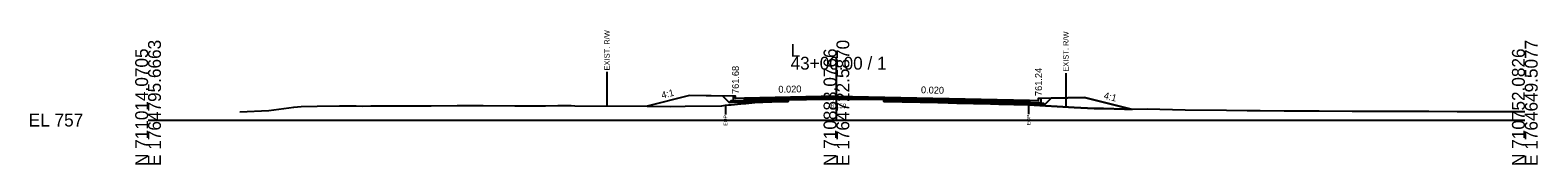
# Model space of a CAD drawing. Extents: x -26 to 5303, y -10 to 9578.
# Drawn here: x 2974.3 to 3302.8, y 2990.3 to 3019.3 of the extents above; entities that cross this region are included whole.
import ezdxf

# ---------------------------------------------------------------- set-up
doc = ezdxf.new("R2010")
doc.units = 0
for name, color, linetype in [('Default', 7, 'Continuous'), ('Exist CMT Pavement', 7, 'Continuous'), ('Exist Cross Section Cell', 7, 'Continuous'), ('Exist XS Ground Line', 7, 'Continuous'), ('Old_Level_10', 7, 'Continuous'), ('Old_Level_3', 7, 'Continuous'), ('Prop CMT Conc Surface', 7, 'Continuous'), ('Prop CMT Concrete Structures', 7, 'Continuous'), ('Prop CMT Pvmt Course 1', 7, 'Continuous'), ('Prop CMT Pvmt Course 1 CG', 7, 'Continuous'), ('Prop CMT Pvmt Course 2', 7, 'Continuous'), ('Prop CMT Pvmt Course 3', 7, 'Continuous'), ('Prop CMT Pvmt Surface', 7, 'Continuous'), ('Prop CMT Slope Grass', 7, 'Continuous'), ('Prop CMT Subgrade Earthwork', 7, 'Continuous'), ('Prop XS Earthwork Shape', 7, 'Continuous'), ('Prop XS Hydro Elevations', 7, 'Continuous'), ('Prop XS SE Text', 7, 'Continuous'), ('Prop XS Side Slope Text', 7, 'Continuous'), ('Prop XS Wedging', 7, 'Continuous')]:
    doc.layers.add(name, color=color, linetype=linetype)

msp = doc.modelspace()

# ---------------------------------------------------------------- linework, layer by layer
at = {"layer": 'Exist CMT Pavement'}
msp.add_lwpolyline([(3139.45, 3004.41), (3140.58, 3004.46), (3141.3, 3004.48), (3142.48, 3004.5), (3143.14, 3004.51), (3143.5, 3004.52), (3144.97, 3004.53), (3146.37, 3004.56), (3146.81, 3004.57), (3147.61, 3004.58), (3148.65, 3004.59), (3149.23, 3004.6), (3150, 3004.59), (3151.27, 3004.57), (3152.33, 3004.56), (3152.74, 3004.56), (3154.16, 3004.58), (3154.95, 3004.57), (3156, 3004.56), (3157.88, 3004.57), (3160.36, 3004.5)], dxfattribs=at)
at = {"layer": 'Exist Cross Section Cell'}
for p, q in [((3150, 3000), (3150, 3013.79)), ((3000, 3000), (3150, 3000)), ((3150, 3000), (3300, 3000))]:
    msp.add_line(p, q, dxfattribs=at)
at = {"layer": 'Exist XS Ground Line'}
msp.add_lwpolyline([(3020, 3001.81), (3026.32, 3002.06), (3031.79, 3002.85), (3033.36, 3002.98), (3036.83, 3003), (3041.72, 3003.07), (3045.38, 3003.07), (3046.62, 3003.04), (3048.56, 3003.08), (3061.71, 3003.14), (3067.38, 3003.15), (3071.61, 3003.15), (3073.02, 3003.15), (3079.91, 3003.12), (3086.59, 3003.12), (3089.29, 3003.15), (3092.22, 3003.15), (3093.03, 3003.14), (3109.61, 3003.06), (3113.8, 3002.98), (3117.01, 3003), (3125.02, 3003.14), (3125.83, 3003.23), (3126.49, 3003.29), (3127.09, 3003.32), (3129.19, 3003.52), (3130.27, 3003.6), (3132.22, 3003.81), (3134.92, 3003.95), (3135.79, 3003.99), (3137.78, 3004.24), (3139.45, 3004.41), (3140.58, 3004.46), (3141.3, 3004.48), (3142.48, 3004.5), (3143.14, 3004.51), (3143.5, 3004.52), (3144.79, 3004.54), (3146.37, 3004.56), (3146.81, 3004.57), (3147.61, 3004.58), (3148.65, 3004.59), (3149.23, 3004.6), (3150, 3004.59), (3151.27, 3004.57), (3152.09, 3004.56), (3152.74, 3004.56), (3154.16, 3004.58), (3154.95, 3004.57), (3156, 3004.56), (3157.88, 3004.57), (3159.68, 3004.57), (3160.68, 3004.5), (3163.01, 3004.31), (3163.54, 3004.28), (3165.19, 3004.18), (3166.41, 3004.12), (3168.14, 3004.05), (3168.86, 3004.01), (3169.27, 3003.98), (3170.7, 3003.92), (3172.13, 3003.86), (3172.54, 3003.84), (3173.27, 3003.81), (3174.38, 3003.78), (3174.99, 3003.76), (3176.21, 3003.72), (3178.05, 3003.68), (3178.4, 3003.67), (3180.72, 3003.6), (3181.73, 3003.58), (3183.64, 3003.54), (3186.44, 3003.48), (3187.24, 3003.46), (3188.66, 3003.43), (3189.02, 3003.42), (3189.97, 3003.38), (3190.45, 3003.37), (3191.88, 3003.32), (3201.79, 3002.72), (3206.14, 3002.55), (3208.18, 3002.54), (3212.8, 3002.38), (3213.27, 3002.4), (3214.51, 3002.39), (3217.82, 3002.46), (3220.46, 3002.39), (3225.98, 3002.24), (3235.01, 3002.15), (3239.48, 3002.1), (3242.36, 3002.1), (3247.53, 3002), (3249.71, 3002.01), (3250.93, 3001.99), (3255.22, 3001.98), (3262.38, 3001.97), (3268.06, 3001.94), (3271.77, 3001.93), (3273.84, 3001.92), (3279.12, 3001.92), (3285.29, 3001.87), (3288.59, 3001.87), (3296.74, 3001.89), (3300, 3001.86)], dxfattribs=at)
at = {"layer": 'Old_Level_10'}
for p, q in [((3100, 3010.51), (3100, 3003.11)), ((3200, 3010.23), (3200, 3002.83)), ((3125.81, 3003.23), (3125.81, 3001.18)), ((3191.88, 3003.32), (3191.88, 3001.27))]:
    msp.add_line(p, q, dxfattribs=at)
at = {"layer": 'Prop CMT Conc Surface'}
for points in [[(3128, 3004.68), (3128, 3005.18), (3127.5, 3005.18)], [(3130, 3004.8), (3128, 3004.68)], [(3192.04, 3004.36), (3194.04, 3004.24)], [(3194.04, 3004.24), (3194.04, 3004.74), (3194.54, 3004.74)]]:
    msp.add_lwpolyline(points, dxfattribs=at)
at = {"layer": 'Prop CMT Concrete Structures'}
for points in [[(3130, 3004.8), (3128, 3004.68), (3128, 3005.18), (3127.5, 3005.18)], [(3127.5, 3005.18), (3127.5, 3004.17), (3130, 3004.22)], [(3130, 3004.22), (3130, 3004.8)], [(3192.04, 3004.36), (3194.04, 3004.24), (3194.04, 3004.74), (3194.54, 3004.74)], [(3194.54, 3004.74), (3194.54, 3003.73), (3192.04, 3003.78)], [(3192.04, 3003.78), (3192.04, 3004.36)]]:
    msp.add_lwpolyline(points, dxfattribs=at)
at = {"layer": 'Prop CMT Pvmt Course 1'}
for points in [[(3150, 3005.2), (3130, 3004.8)], [(3130, 3004.8), (3130, 3004.55)], [(3130, 3004.55), (3139.45, 3004.74)], [(3139.45, 3004.74), (3150, 3004.95)], [(3139.45, 3004.74), (3139.45, 3004.74)], [(3150, 3004.95), (3150, 3005.2)], [(3150, 3005.2), (3192.04, 3004.36)], [(3150, 3004.95), (3150, 3004.95), (3150, 3004.95)], [(3160.36, 3004.75), (3150, 3004.95)], [(3192.04, 3004.11), (3160.36, 3004.75)], [(3160.36, 3004.75), (3160.36, 3004.75)], [(3192.04, 3004.36), (3192.04, 3004.11)]]:
    msp.add_lwpolyline(points, dxfattribs=at)
at = {"layer": 'Prop CMT Pvmt Course 1 CG'}
for points in [[(3130, 3004.22), (3127, 3004.16), (3126.66, 3003.82)], [(3126.66, 3003.82), (3130, 3003.89)], [(3130, 3003.89), (3130, 3004.22)], [(3192.04, 3003.78), (3195.04, 3003.72), (3195.38, 3003.38)], [(3192.04, 3003.45), (3192.04, 3003.78)], [(3195.38, 3003.38), (3192.04, 3003.45)]]:
    msp.add_lwpolyline(points, dxfattribs=at)
at = {"layer": 'Prop CMT Pvmt Course 2'}
for points in [[(3139.45, 3004.74), (3130, 3004.55)], [(3130, 3004.55), (3130, 3004.22)], [(3130, 3004.22), (3139.45, 3004.41)], [(3139.45, 3004.41), (3139.45, 3004.74)], [(3160.36, 3004.41), (3160.36, 3004.75)], [(3160.36, 3004.75), (3192.04, 3004.11)], [(3192.04, 3003.78), (3160.36, 3004.41)], [(3192.04, 3004.11), (3192.04, 3003.78)]]:
    msp.add_lwpolyline(points, dxfattribs=at)
at = {"layer": 'Prop CMT Pvmt Course 3'}
for points in [[(3139.45, 3004.41), (3130, 3004.22)], [(3130, 3004.22), (3130, 3003.89)], [(3130, 3003.89), (3139.45, 3004.08)], [(3139.45, 3004.08), (3139.45, 3004.41)], [(3160.36, 3004.41), (3192.04, 3003.78)], [(3160.36, 3004.08), (3160.36, 3004.41)], [(3192.04, 3003.45), (3160.36, 3004.08)], [(3192.04, 3003.78), (3192.04, 3003.45)]]:
    msp.add_lwpolyline(points, dxfattribs=at)
at = {"layer": 'Prop CMT Pvmt Surface'}
for points in [[(3150, 3005.2), (3130, 3004.8)], [(3150, 3005.2), (3192.04, 3004.36)]]:
    msp.add_lwpolyline(points, dxfattribs=at)
at = {"layer": 'Prop CMT Slope Grass'}
for points in [[(3127.5, 3005.18), (3118, 3005.37), (3108.76, 3003.06)], [(3194.54, 3004.74), (3204.04, 3004.93), (3214.2, 3002.39)]]:
    msp.add_lwpolyline(points, dxfattribs=at)
at = {"layer": 'Prop CMT Subgrade Earthwork'}
for p, q in [((3139.45, 3004.08), (3139.45, 3004.41)), ((3160.36, 3004.08), (3160.36, 3004.5))]:
    msp.add_line(p, q, dxfattribs=at)
for points in [[(3130, 3003.89), (3126.66, 3003.82), (3125.25, 3005.23)], [(3139.45, 3004.08), (3130, 3003.89)], [(3160.36, 3004.08), (3192.04, 3003.45)], [(3192.04, 3003.45), (3195.38, 3003.38), (3196.79, 3004.79)]]:
    msp.add_lwpolyline(points, dxfattribs=at)
at = {"layer": 'Prop XS Earthwork Shape'}
for points in [[(3108.76, 3003.06), (3109.61, 3003.06), (3113.8, 3002.98), (3117.01, 3003), (3125.02, 3003.14), (3125.83, 3003.23), (3126.49, 3003.29), (3127.09, 3003.32), (3129.19, 3003.52), (3130.27, 3003.6), (3132.22, 3003.81), (3133.95, 3003.91), (3134.92, 3003.95), (3135.79, 3003.99), (3135.92, 3004.01), (3130, 3003.89), (3126.66, 3003.82), (3125.25, 3005.23), (3118, 3005.37)], [(3125.25, 3005.23), (3118, 3005.37), (3108.76, 3003.06), (3109.61, 3003.06), (3113.8, 3002.98), (3117.01, 3003), (3125.02, 3003.14), (3125.83, 3003.23), (3126.49, 3003.29), (3127.09, 3003.32), (3129.19, 3003.52), (3130.27, 3003.6), (3132.22, 3003.81), (3133.95, 3003.91), (3134.92, 3003.95), (3135.79, 3003.99), (3135.92, 3004.01), (3130, 3003.89), (3126.66, 3003.82)], [(3137.78, 3004.24), (3139.45, 3004.41), (3139.45, 3004.08), (3135.92, 3004.01), (3137.35, 3004.19)], [(3139.45, 3004.08), (3139.45, 3004.41), (3137.78, 3004.24), (3137.35, 3004.19), (3135.92, 3004.01)], [(3160.36, 3004.08), (3160.36, 3004.5), (3160.68, 3004.5), (3161.51, 3004.42), (3163.01, 3004.31), (3163.54, 3004.28), (3165.19, 3004.18), (3166.41, 3004.12), (3167.03, 3004.1), (3168.14, 3004.05), (3168.86, 3004.01), (3169.27, 3003.98), (3170.7, 3003.92), (3172.13, 3003.86), (3172.54, 3003.84)], [(3166.41, 3004.12), (3167.03, 3004.1), (3168.14, 3004.05), (3168.86, 3004.01), (3169.27, 3003.98), (3170.7, 3003.92), (3172.13, 3003.86), (3172.54, 3003.84), (3160.36, 3004.08), (3160.36, 3004.5), (3160.68, 3004.5), (3161.51, 3004.42), (3163.01, 3004.31), (3163.54, 3004.28), (3165.19, 3004.18)], [(3204.04, 3004.93), (3214.2, 3002.39), (3213.27, 3002.4), (3212.8, 3002.38), (3208.18, 3002.54), (3206.14, 3002.55), (3201.79, 3002.72), (3191.88, 3003.32), (3190.45, 3003.37), (3189.97, 3003.38), (3189.02, 3003.42), (3188.66, 3003.43), (3187.24, 3003.46), (3186.44, 3003.48), (3185.4, 3003.5), (3183.58, 3003.54), (3181.73, 3003.58), (3180.72, 3003.6), (3179.89, 3003.63), (3178.4, 3003.67), (3178.05, 3003.68), (3176.21, 3003.72), (3174.99, 3003.76), (3174.38, 3003.78), (3173.27, 3003.81), (3172.54, 3003.84), (3192.04, 3003.45), (3195.38, 3003.38), (3196.79, 3004.79)], [(3189.02, 3003.42), (3189.97, 3003.38), (3190.45, 3003.37), (3191.88, 3003.32), (3201.79, 3002.72), (3206.14, 3002.55), (3208.18, 3002.54), (3212.8, 3002.38), (3213.27, 3002.4), (3214.2, 3002.39), (3204.04, 3004.93), (3196.79, 3004.79), (3195.38, 3003.38), (3192.04, 3003.45), (3172.54, 3003.84), (3173.27, 3003.81), (3174.38, 3003.78), (3174.99, 3003.76), (3176.21, 3003.72), (3178.05, 3003.68), (3178.4, 3003.67), (3179.89, 3003.63), (3180.72, 3003.6), (3181.73, 3003.58), (3183.58, 3003.54), (3185.4, 3003.5), (3186.44, 3003.48), (3187.24, 3003.46), (3188.66, 3003.43)]]:
    msp.add_lwpolyline(points, close=True, dxfattribs=at)
at = {"layer": 'Prop XS Wedging'}
msp.add_lwpolyline([(3139.45, 3004.41), (3139.45, 3004.74), (3140.58, 3004.76), (3141.3, 3004.78), (3142.48, 3004.8), (3143.14, 3004.82), (3143.5, 3004.82), (3144.97, 3004.85), (3146.37, 3004.88), (3146.81, 3004.89), (3147.61, 3004.91), (3148.65, 3004.93), (3149.23, 3004.94), (3150, 3004.95), (3151.27, 3004.93), (3152.33, 3004.91), (3152.74, 3004.9), (3154.16, 3004.87), (3154.95, 3004.85), (3156, 3004.83), (3157.88, 3004.8), (3160.68, 3004.74), (3160.68, 3004.49), (3157.88, 3004.57), (3156, 3004.56), (3154.95, 3004.57), (3154.16, 3004.58), (3152.74, 3004.56), (3152.33, 3004.56), (3151.27, 3004.57), (3150, 3004.59), (3149.23, 3004.6), (3148.65, 3004.59), (3147.61, 3004.58), (3146.81, 3004.57), (3146.37, 3004.56), (3144.97, 3004.53), (3143.5, 3004.52), (3143.14, 3004.51), (3142.48, 3004.5), (3141.3, 3004.48), (3140.58, 3004.46)], close=True, dxfattribs=at)

# ---------------------------------------------------------------- texts
at = {"layer": 'Default'}
msp.add_text('-', height=0.0001, dxfattribs=at).set_placement((3000, 3000))
at = {"layer": 'Exist Cross Section Cell'}
for s, p in [('E 1764795.6663', (3002.8, 2990)), ('E 1764722.5870', (3152.8, 2990)), ('E 1764649.5077', (3302.8, 2990)), ('N 711014.0705', (3000, 2990)), ('N 710883.0766', (3150, 2990)), ('N 710752.0826', (3300, 2990))]:
    msp.add_text(s, height=2.8, rotation=90, dxfattribs=at).set_placement(p)
for s, p in [('L', (3140, 3013.79)), ('43+00.00 / 1', (3140, 3010.99)), ('EL 757', (2974, 2998.6))]:
    msp.add_text(s, height=2.8, dxfattribs=at).set_placement(p)
at = {"layer": 'Old_Level_10'}
for s, height, p in [('EXIST. R/W', 1.181, (3100.59, 3010.81)), ('EXIST. R/W', 1.181, (3200.59, 3010.53)), ('EOP', 0.787, (3126.21, 2998.78)), ('EOP', 0.787, (3192.28, 2998.87))]:
    msp.add_text(s, height=height, rotation=90, dxfattribs=at).set_placement(p)
at = {"layer": 'Old_Level_3'}
msp.add_text('761.59', height=1, dxfattribs=at).set_placement((3147.95, 3002.59))
at = {"layer": 'Prop XS Hydro Elevations'}
for s, p in [('761.68', (3128.75, 3005.68)), ('761.24', (3194.79, 3005.24))]:
    msp.add_text(s, height=1.5, rotation=90, dxfattribs=at).set_placement(p)
at = {"layer": 'Prop XS SE Text'}
for rotation, p in [(1.1458, (3137.36, 3005.95)), (358.8542, (3168.41, 3005.84))]:
    msp.add_text('0.020', height=1.5, rotation=rotation, dxfattribs=at).set_placement(p)
at = {"layer": 'Prop XS Side Slope Text'}
for rotation, p in [(14.0362, (3112.04, 3004.66)), (345.9638, (3208.15, 3004.68))]:
    msp.add_text('4:1', height=1.5, rotation=rotation, dxfattribs=at).set_placement(p)

doc.saveas('drawing.dxf')
